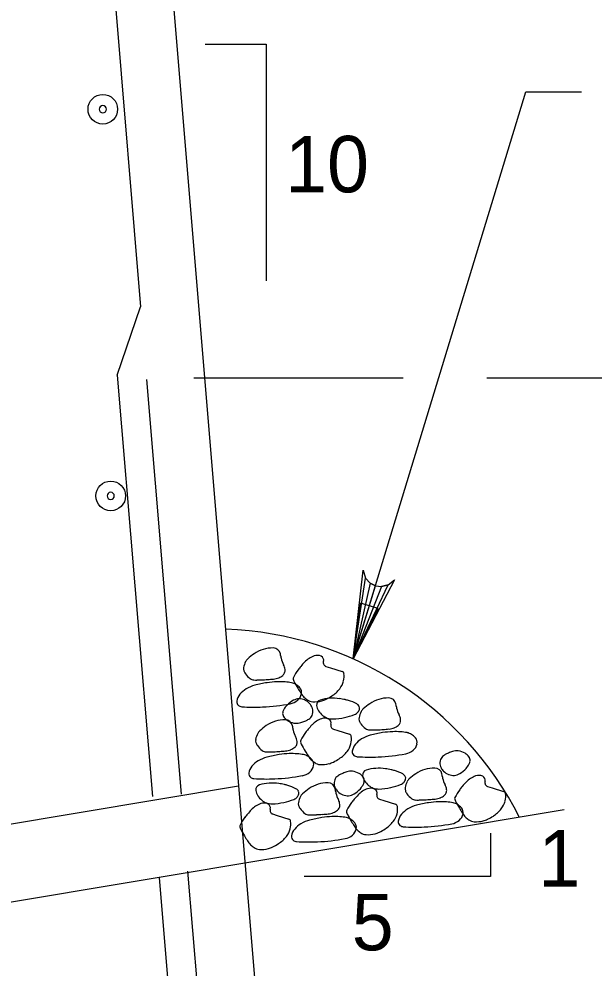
# Model space of a CAD drawing. Extents: x 179 to 454, y -271 to 54.
# Drawn here: x 237.413 to 238.636, y -94.851 to -92.833 of the extents above; entities that cross this region are included whole.
import ezdxf

# ---------------------------------------------------------------- set-up
doc = ezdxf.new("R2010")
doc.units = 0
for name, color, linetype in [('Level 3', 7, 'Continuous'), ('Level 5', 7, 'Continuous'), ('Level 8', 7, 'Continuous'), ('Level 9', 7, 'Continuous')]:
    doc.layers.add(name, color=color, linetype=linetype)

# ---------------------------------------------------------------- blocks, each defined once
blk = doc.blocks.new('B')
at = {"layer": 'Level 3'}
blk.add_circle((0, 0), 0.1066, dxfattribs=at)
for start, end in [(0, 180), (180, 0)]:
    blk.add_arc((0, 0), 0.026, start, end, dxfattribs=at)

msp = doc.modelspace()

# ---------------------------------------------------------------- linework, layer by layer
at = {"layer": 'Level 3'}
for p, q in [((238.1238, -94.194), (238.4913, -92.9877)), ((238.4913, -92.9877), (238.6094, -92.9877)), ((237.7849, -93.5961), (238.2298, -93.5961)), ((238.408, -93.5961), (239.872, -93.5961))]:
    msp.add_line(p, q, dxfattribs=at)
for points in [[(238.1238, -94.194), (238.1447, -94.0055), (238.1501, -94.0222), (238.1598, -94.0328), (238.1712, -94.0386), (238.1838, -94.0402), (238.1979, -94.0367), (238.2116, -94.0258), (238.1238, -94.194), (238.1979, -94.0367), (238.1838, -94.0402), (238.1238, -94.194), (238.1712, -94.0386), (238.1598, -94.0328), (238.1238, -94.194), (238.1501, -94.0222)], [(238.416, -94.5643), (238.416, -94.6567), (238.0191, -94.6567)]]:
    msp.add_lwpolyline(points, dxfattribs=at)
msp.add_lwpolyline([(238.1771, -94.0867), (238.1394, -94.0753), (238.1238, -94.194)], close=True, dxfattribs=at)
at = {"layer": 'Level 5'}
for p, q in [((237.5272, -91.7143), (237.6715, -93.4455)), ((237.6218, -93.5904), (237.6715, -93.4455)), ((237.6218, -93.5904), (237.6965, -94.4864)), ((237.6843, -93.5998), (237.7578, -94.4813)), ((237.7715, -94.6452), (237.9778, -97.1208)), ((237.7109, -94.6589), (237.8529, -96.3632))]:
    msp.add_line(p, q, dxfattribs=at)
at = {"layer": 'Level 8'}
for points in [[(238.0658, -94.2097), (238.0756, -94.2128), (238.1, -94.2205)], [(238.0815, -94.3432), (238.0913, -94.3463), (238.1157, -94.3541)], [(238.4095, -94.4649), (238.4193, -94.468), (238.4437, -94.4757)], [(238.1794, -94.4922), (238.1892, -94.4953), (238.2137, -94.5031)], [(237.9523, -94.5237), (237.9622, -94.5268), (237.9866, -94.5346)]]:
    msp.add_lwpolyline(points, dxfattribs=at)
for centre, radius, start, end in [((237.9791, -94.2804), 0.1177, 124.1443, 132.7374), ((237.9529, -94.2417), 0.0711, 89.5772, 124.1443), ((237.9533, -94.1865), 0.0158, 11.4529, 89.5772), ((237.9159, -94.1941), 0.054, 6.1004, 11.4529), ((238.0057, -94.1845), 0.0363, 186.1004, 192.6291), ((238.058, -94.2365), 0.0519, 109.6635, 136.4562), ((238.0473, -94.2065), 0.0201, 65.9597, 109.6635), ((238.0517, -94.1966), 0.00925, 342.3569, 65.9597), ((237.9408, -94.2226), 0.0514, 153.538, 168.4897), ((237.913, -94.2088), 0.0203, 132.7374, 153.538), ((238.0223, -94.1807), 0.0533, 192.6291, 208.6753), ((237.9511, -94.2197), 0.0278, 6.391, 28.6753), ((238.0974, -94.2824), 0.112, 139.6491, 144.1424), ((238.1811, -94.3535), 0.2218, 136.4562, 139.6491), ((238.0683, -94.2019), 0.0082, 162.3569, 252.4715), ((237.9027, -94.2149), 0.0124, 168.4897, 199.1639), ((237.9119, -94.2117), 0.0222, 199.1639, 207.4728), ((237.9236, -94.2056), 0.0354, 207.4728, 214.0468), ((237.9293, -94.2018), 0.0422, 214.0468, 234.0353), ((237.9547, -94.2071), 0.029, 291.5731, 310.9894), ((237.9639, -94.2177), 0.015, 310.9894, 338.0834), ((237.9651, -94.2181), 0.0138, 338.0834, 6.391), ((238.1187, -94.2978), 0.1383, 144.1424, 152.1777), ((238.0983, -94.2262), 0.00592, 9.0416, 72.4715), ((238.067, -94.2311), 0.0375, 344.9373, 9.0416), ((237.9331, -94.32), 0.0724, 104.9239, 120.8473), ((237.9131, -94.224), 0.0147, 234.0353, 268.2715), ((237.9167, -94.1039), 0.1349, 268.2715, 270.9097), ((237.9812, -94.5007), 0.2594, 99.0416, 104.9239), ((237.9133, -93.889), 0.3498, 270.9097, 272.5478), ((237.9034, -93.6662), 0.5728, 272.5478, 273.846), ((237.9673, -94.4131), 0.1707, 91.7881, 99.0416), ((237.9071, -93.7211), 0.5178, 273.846, 275.2114), ((237.9504, -94.1962), 0.0408, 275.2114, 291.5731), ((237.9672, -94.4105), 0.1681, 86.0442, 91.7881), ((237.9711, -94.355), 0.1125, 79.021, 86.0442), ((237.9872, -94.272), 0.0279, 58.4341, 79.021), ((238.0012, -94.2358), 0.00543, 152.1777, 193.5774), ((238.0147, -94.2325), 0.0193, 193.5774, 207.4728), ((238.2279, -94.1217), 0.2596, 207.4728, 211.2525), ((237.9825, -94.2796), 0.0368, 40.5338, 58.4341), ((238.059, -94.229), 0.0459, 321.7572, 344.9373), ((237.9042, -94.2876), 0.0285, 139.2037, 172.3458), ((237.9239, -94.3047), 0.0546, 120.8473, 139.2037), ((237.99, -94.2634), 0.0242, 309.5539, 349.0625), ((238.5991, -93.8964), 0.6938, 211.2525, 212.2356), ((237.9994, -94.2652), 0.0146, 349.0625, 40.5338), ((238.14, -94.1859), 0.1511, 212.2356, 214.3424), ((238.0399, -94.2139), 0.0702, 303.0692, 321.7572), ((237.8858, -94.2852), 0.00988, 172.3458, 230.2635), ((237.9143, -93.8934), 0.4031, 272.3841, 280.7777), ((238.0205, -94.3279), 0.0518, 117.4803, 136.4654), ((237.9831, -94.255), 0.035, 280.7777, 309.5539), ((238.0093, -94.3064), 0.0276, 91.376, 117.4803), ((238.0093, -94.306), 0.0272, 65.3457, 91.376), ((238.0343, -94.2582), 0.023, 214.3424, 227.6953), ((238.0665, -94.2227), 0.0709, 227.6953, 235.2847), ((238.0076, -94.3097), 0.0312, 41.057, 65.3457), ((238.0391, -94.2623), 0.0228, 235.2847, 266.0442), ((238.0037, -94.3131), 0.0364, 27.4728, 41.057), ((238.0415, -94.2276), 0.0575, 266.0442, 285.2565), ((238.0567, -94.292), 0.011, 106.8084, 186.6218), ((238.0804, -94.3705), 0.0931, 81.3134, 106.8084), ((238.0424, -94.231), 0.054, 285.2565, 295.7443), ((238.0179, -94.1801), 0.1106, 295.7443, 303.0692), ((238.0572, -94.5221), 0.2465, 78.4814, 81.3134), ((238.0882, -94.3701), 0.0913, 73.8272, 78.4814), ((238.0899, -94.3644), 0.0854, 61.1605, 73.8272), ((238.1242, -94.3021), 0.0143, 29.8544, 61.1605), ((238.2249, -94.3866), 0.1177, 124.1443, 132.7374), ((238.1987, -94.348), 0.0711, 89.5772, 124.1443), ((238.1991, -94.2927), 0.0158, 11.4529, 89.5772), ((238.1617, -94.3003), 0.054, 6.1004, 11.4529), ((237.8874, -94.2831), 0.0125, 230.2635, 266.2346), ((237.9138, -93.8823), 0.4142, 266.2346, 272.3841), ((237.9872, -94.3095), 0.0136, 171.9761, 209.5935), ((237.9902, -94.3099), 0.0166, 149.2422, 171.9761), ((238.0206, -94.328), 0.052, 136.4654, 149.2422), ((238.0202, -94.3045), 0.0179, 8.0357, 27.4728), ((238.0151, -94.3052), 0.023, 337.0418, 8.0357), ((238.069, -94.2905), 0.0234, 186.6218, 200.3491), ((238.0737, -94.2888), 0.0285, 200.3491, 212.797), ((238.0867, -94.2804), 0.0439, 212.797, 230.2213), ((238.1192, -94.2939), 0.0197, 292.039, 317.8475), ((238.1227, -94.297), 0.015, 317.8475, 347.2445), ((238.1866, -94.3289), 0.0514, 153.538, 168.4897), ((238.1302, -94.2987), 0.00733, 347.2445, 29.8544), ((238.1588, -94.315), 0.0203, 132.7374, 153.538), ((238.2514, -94.2907), 0.0363, 186.1004, 192.6291), ((238.2681, -94.287), 0.0533, 192.6291, 208.6753), ((237.9787, -94.3946), 0.0711, 89.5772, 124.1443), ((237.9963, -94.3043), 0.024, 209.5935, 237.6667), ((237.9791, -94.3393), 0.0158, 11.4529, 89.5772), ((238.0054, -94.29), 0.041, 237.6667, 259.0544), ((238.0026, -94.3042), 0.0265, 259.0544, 285.7584), ((237.9575, -94.1446), 0.1924, 285.7584, 288.5059), ((238.0026, -94.2791), 0.0505, 288.5059, 293.8705), ((238.0046, -94.2838), 0.0454, 293.8705, 297.4803), ((237.9762, -94.2291), 0.107, 297.4803, 299.831), ((238.0214, -94.3079), 0.0162, 299.831, 337.0418), ((238.0737, -94.37), 0.0519, 109.6635, 136.4562), ((238.0629, -94.3401), 0.0201, 65.9597, 109.6635), ((238.0793, -94.2893), 0.0323, 230.2213, 250.5601), ((238.0792, -94.2895), 0.0321, 250.5601, 271.915), ((238.0674, -94.3301), 0.00925, 342.3569, 65.9597), ((238.0754, -94.1754), 0.1463, 271.915, 281.8686), ((238.0798, -94.1965), 0.1247, 281.8686, 292.039), ((238.1484, -94.3211), 0.0124, 168.4897, 199.1639), ((238.1576, -94.3179), 0.0222, 199.1639, 207.4728), ((238.1693, -94.3118), 0.0354, 207.4728, 214.0468), ((238.2097, -94.3239), 0.015, 310.9894, 338.0834), ((238.1969, -94.3259), 0.0278, 6.391, 28.6753), ((238.2108, -94.3243), 0.0138, 338.0834, 6.391), ((237.9387, -94.3616), 0.0203, 132.7374, 153.538), ((238.0049, -94.4332), 0.1177, 124.1443, 132.7374), ((237.9417, -94.3469), 0.054, 6.1004, 11.4529), ((238.0314, -94.3373), 0.0363, 186.1004, 192.6291), ((238.048, -94.3336), 0.0533, 192.6291, 208.6753), ((238.1344, -94.4314), 0.1383, 144.1424, 152.1777), ((238.1131, -94.416), 0.112, 139.6491, 144.1424), ((238.1968, -94.4871), 0.2218, 136.4562, 139.6491), ((238.084, -94.3354), 0.0082, 162.3569, 252.4715), ((238.175, -94.308), 0.0422, 214.0468, 234.0353), ((238.1588, -94.3303), 0.0147, 234.0353, 268.2715), ((238.1625, -94.2101), 0.1349, 268.2715, 270.9097), ((238.227, -94.6069), 0.2594, 99.0416, 104.9239), ((238.1591, -93.9952), 0.3498, 270.9097, 272.5478), ((238.1491, -93.7725), 0.5728, 272.5478, 273.846), ((238.2131, -94.5193), 0.1707, 91.7881, 99.0416), ((238.1528, -93.8273), 0.5178, 273.846, 275.2114), ((238.1962, -94.3024), 0.0408, 275.2114, 291.5731), ((238.213, -94.5167), 0.1681, 86.0442, 91.7881), ((238.2005, -94.3133), 0.029, 291.5731, 310.9894), ((238.2168, -94.4612), 0.1125, 79.021, 86.0442), ((238.2329, -94.3782), 0.0279, 58.4341, 79.021), ((237.9284, -94.3677), 0.0124, 168.4897, 199.1639), ((237.9665, -94.3755), 0.0514, 153.538, 168.4897), ((237.9376, -94.3645), 0.0222, 199.1639, 207.4728), ((237.9768, -94.3725), 0.0278, 6.391, 28.6753), ((237.9908, -94.371), 0.0138, 338.0834, 6.391), ((238.0169, -94.3693), 0.00543, 152.1777, 193.5774), ((238.0304, -94.3661), 0.0193, 193.5774, 207.4728), ((238.114, -94.3597), 0.00592, 9.0416, 72.4715), ((238.0827, -94.3647), 0.0375, 344.9373, 9.0416), ((238.1697, -94.4109), 0.0546, 120.8473, 139.2037), ((238.1788, -94.4262), 0.0724, 104.9239, 120.8473), ((238.2283, -94.3858), 0.0368, 40.5338, 58.4341), ((238.2451, -94.3714), 0.0146, 349.0625, 40.5338), ((237.9493, -94.3584), 0.0354, 207.4728, 214.0468), ((237.955, -94.3546), 0.0422, 214.0468, 234.0353), ((237.9388, -94.3769), 0.0147, 234.0353, 268.2715), ((237.9424, -94.2568), 0.1349, 268.2715, 270.9097), ((237.939, -94.0418), 0.3498, 270.9097, 272.5478), ((237.9291, -93.8191), 0.5728, 272.5478, 273.846), ((237.9328, -93.8739), 0.5178, 273.846, 275.2114), ((237.9761, -94.349), 0.0408, 275.2114, 291.5731), ((237.9804, -94.3599), 0.029, 291.5731, 310.9894), ((237.9896, -94.3705), 0.015, 310.9894, 338.0834), ((238.2436, -94.2552), 0.2596, 207.4728, 211.2525), ((238.6148, -94.03), 0.6938, 211.2525, 212.2356), ((238.0556, -94.3474), 0.0702, 303.0692, 321.7572), ((238.0747, -94.3625), 0.0459, 321.7572, 344.9373), ((238.15, -94.3939), 0.0285, 139.2037, 172.3458), ((238.1315, -94.3914), 0.00988, 172.3458, 230.2635), ((238.2289, -94.3613), 0.035, 280.7777, 309.5539), ((238.2358, -94.3696), 0.0242, 309.5539, 349.0625), ((238.3973, -94.5729), 0.1924, 108.8812, 111.6288), ((238.3436, -94.4159), 0.0265, 82.1773, 108.8812), ((238.3416, -94.4303), 0.041, 60.7895, 82.1773), ((237.9497, -94.4575), 0.0546, 120.8473, 139.2037), ((237.9588, -94.4728), 0.0724, 104.9239, 120.8473), ((238.007, -94.6535), 0.2594, 99.0416, 104.9239), ((237.993, -94.5659), 0.1707, 91.7881, 99.0416), ((237.9929, -94.5634), 0.1681, 86.0442, 91.7881), ((237.9968, -94.5079), 0.1125, 79.021, 86.0442), ((238.0129, -94.4248), 0.0279, 58.4341, 79.021), ((238.0082, -94.4324), 0.0368, 40.5338, 58.4341), ((238.1557, -94.3194), 0.1511, 212.2356, 214.3424), ((238.0499, -94.3917), 0.023, 214.3424, 227.6953), ((238.0822, -94.3562), 0.0709, 227.6953, 235.2847), ((238.0251, -94.418), 0.0146, 349.0625, 40.5338), ((238.0336, -94.3136), 0.1106, 295.7443, 303.0692), ((238.1332, -94.3894), 0.0125, 230.2635, 266.2346), ((238.1596, -93.9885), 0.4142, 266.2346, 272.3841), ((238.1601, -93.9996), 0.4031, 272.3841, 280.7777), ((238.3311, -94.4156), 0.023, 160.1647, 191.1585), ((238.3247, -94.4133), 0.0162, 122.9538, 160.1647), ((238.3741, -94.4895), 0.107, 120.6031, 122.9538), ((238.3427, -94.4365), 0.0454, 116.9933, 120.6031), ((238.345, -94.441), 0.0505, 111.6288, 116.9933), ((238.3499, -94.4155), 0.024, 32.7163, 60.7895), ((238.3587, -94.4098), 0.0136, 355.0989, 32.7163), ((238.3557, -94.4096), 0.0166, 332.365, 355.0989), ((237.9299, -94.4405), 0.0285, 139.2037, 172.3458), ((238.0157, -94.4162), 0.0242, 309.5539, 349.0625), ((238.0548, -94.3958), 0.0228, 235.2847, 266.0442), ((238.0572, -94.3612), 0.0575, 266.0442, 285.2565), ((238.0581, -94.3646), 0.054, 285.2565, 295.7443), ((238.1546, -94.441), 0.011, 106.8084, 186.6218), ((238.1783, -94.5195), 0.0931, 81.3134, 106.8084), ((238.1552, -94.6711), 0.2465, 78.4814, 81.3134), ((238.1862, -94.5191), 0.0913, 73.8272, 78.4814), ((238.1878, -94.5134), 0.0854, 61.1605, 73.8272), ((238.2966, -94.497), 0.0711, 89.5772, 124.1443), ((238.297, -94.4417), 0.0158, 11.4529, 89.5772), ((238.3261, -94.4166), 0.0179, 191.1585, 210.5956), ((238.342, -94.4071), 0.0364, 210.5956, 224.1798), ((238.3245, -94.3933), 0.0518, 300.6031, 319.5882), ((238.3243, -94.3932), 0.052, 319.5882, 332.365), ((237.9115, -94.438), 0.00988, 172.3458, 230.2635), ((237.9132, -94.436), 0.0125, 230.2635, 266.2346), ((237.9396, -94.0351), 0.4142, 266.2346, 272.3841), ((237.94, -94.0462), 0.4031, 272.3841, 280.7777), ((238.0089, -94.4079), 0.035, 280.7777, 309.5539), ((238.1061, -94.4588), 0.023, 160.1647, 191.1585), ((238.0996, -94.4565), 0.0162, 122.9538, 160.1647), ((238.1491, -94.5327), 0.107, 120.6031, 122.9538), ((238.1177, -94.4797), 0.0454, 116.9933, 120.6031), ((238.12, -94.4842), 0.0505, 111.6288, 116.9933), ((238.1723, -94.6161), 0.1924, 108.8812, 111.6288), ((238.1186, -94.4591), 0.0265, 82.1773, 108.8812), ((238.1166, -94.4735), 0.041, 60.7895, 82.1773), ((238.1249, -94.4587), 0.024, 32.7163, 60.7895), ((238.1669, -94.4395), 0.0234, 186.6218, 200.3491), ((238.1717, -94.4378), 0.0285, 200.3491, 212.797), ((238.1337, -94.453), 0.0136, 355.0989, 32.7163), ((238.2221, -94.4511), 0.0143, 29.8544, 61.1605), ((238.2206, -94.446), 0.015, 317.8475, 347.2445), ((238.2281, -94.4477), 0.00733, 347.2445, 29.8544), ((238.2567, -94.464), 0.0203, 132.7374, 153.538), ((238.3228, -94.5356), 0.1177, 124.1443, 132.7374), ((238.2596, -94.4493), 0.054, 6.1004, 11.4529), ((238.3494, -94.4397), 0.0363, 186.1004, 192.6291), ((238.366, -94.436), 0.0533, 192.6291, 208.6753), ((238.3383, -94.4108), 0.0312, 224.1798, 248.4685), ((238.3368, -94.4145), 0.0272, 248.4685, 274.4988), ((238.3368, -94.4141), 0.0276, 274.4988, 300.6031), ((238.4017, -94.4917), 0.0519, 109.6635, 136.4562), ((238.391, -94.4617), 0.0201, 65.9597, 109.6635), ((238.3954, -94.4518), 0.00925, 342.3569, 65.9597), ((237.9275, -94.4724), 0.011, 106.8084, 186.6218), ((237.9513, -94.551), 0.0931, 81.3134, 106.8084), ((237.9281, -94.7026), 0.2465, 78.4814, 81.3134), ((237.9591, -94.5506), 0.0913, 73.8272, 78.4814), ((237.9607, -94.5449), 0.0854, 61.1605, 73.8272), ((237.995, -94.4826), 0.0143, 29.8544, 61.1605), ((238.0958, -94.5671), 0.1177, 124.1443, 132.7374), ((238.0696, -94.5285), 0.0711, 89.5772, 124.1443), ((238.07, -94.4732), 0.0158, 11.4529, 89.5772), ((238.1011, -94.4598), 0.0179, 191.1585, 210.5956), ((238.0326, -94.4808), 0.054, 6.1004, 11.4529), ((238.117, -94.4504), 0.0364, 210.5956, 224.1798), ((238.0995, -94.4365), 0.0518, 300.6031, 319.5882), ((238.1716, -94.519), 0.0519, 109.6635, 136.4562), ((238.0993, -94.4364), 0.052, 319.5882, 332.365), ((238.1307, -94.4528), 0.0166, 332.365, 355.0989), ((238.1846, -94.4294), 0.0439, 212.797, 230.2213), ((238.1609, -94.4891), 0.0201, 65.9597, 109.6635), ((238.1772, -94.4383), 0.0323, 230.2213, 250.5601), ((238.1771, -94.4385), 0.0321, 250.5601, 271.915), ((238.1653, -94.4791), 0.00925, 342.3569, 65.9597), ((238.1733, -94.3244), 0.1463, 271.915, 281.8686), ((238.1778, -94.3455), 0.1247, 281.8686, 292.039), ((238.2172, -94.4429), 0.0197, 292.039, 317.8475), ((238.2464, -94.4701), 0.0124, 168.4897, 199.1639), ((238.2845, -94.4779), 0.0514, 153.538, 168.4897), ((238.2948, -94.4749), 0.0278, 6.391, 28.6753), ((238.3088, -94.4733), 0.0138, 338.0834, 6.391), ((238.4624, -94.553), 0.1383, 144.1424, 152.1777), ((238.4411, -94.5376), 0.112, 139.6491, 144.1424), ((238.5248, -94.6087), 0.2218, 136.4562, 139.6491), ((238.412, -94.4571), 0.0082, 162.3569, 252.4715), ((237.9399, -94.471), 0.0234, 186.6218, 200.3491), ((237.9446, -94.4693), 0.0285, 200.3491, 212.797), ((237.9575, -94.4609), 0.0439, 212.797, 230.2213), ((237.9507, -94.377), 0.1247, 281.8686, 292.039), ((237.9901, -94.4744), 0.0197, 292.039, 317.8475), ((237.9935, -94.4775), 0.015, 317.8475, 347.2445), ((238.0574, -94.5094), 0.0514, 153.538, 168.4897), ((238.001, -94.4792), 0.00733, 347.2445, 29.8544), ((238.0296, -94.4955), 0.0203, 132.7374, 153.538), ((238.1223, -94.4712), 0.0363, 186.1004, 192.6291), ((238.1389, -94.4675), 0.0533, 192.6291, 208.6753), ((238.1133, -94.454), 0.0312, 224.1798, 248.4685), ((238.1118, -94.4577), 0.0272, 248.4685, 274.4988), ((238.1118, -94.4573), 0.0276, 274.4988, 300.6031), ((238.2111, -94.565), 0.112, 139.6491, 144.1424), ((238.2948, -94.6361), 0.2218, 136.4562, 139.6491), ((238.182, -94.4844), 0.0082, 162.3569, 252.4715), ((238.2556, -94.4669), 0.0222, 199.1639, 207.4728), ((238.2673, -94.4608), 0.0354, 207.4728, 214.0468), ((238.273, -94.457), 0.0422, 214.0468, 234.0353), ((238.2568, -94.4793), 0.0147, 234.0353, 268.2715), ((238.2508, -93.9763), 0.5178, 273.846, 275.2114), ((238.2941, -94.4514), 0.0408, 275.2114, 291.5731), ((238.2984, -94.4623), 0.029, 291.5731, 310.9894), ((238.3076, -94.4729), 0.015, 310.9894, 338.0834), ((238.3449, -94.491), 0.00543, 152.1777, 193.5774), ((238.3584, -94.4878), 0.0193, 193.5774, 207.4728), ((238.442, -94.4814), 0.00592, 9.0416, 72.4715), ((238.4108, -94.4863), 0.0375, 344.9373, 9.0416), ((237.9445, -94.5505), 0.0519, 109.6635, 136.4562), ((237.9338, -94.5205), 0.0201, 65.9597, 109.6635), ((237.9501, -94.4698), 0.0323, 230.2213, 250.5601), ((237.9501, -94.47), 0.0321, 250.5601, 271.915), ((237.9382, -94.5106), 0.00925, 342.3569, 65.9597), ((237.9462, -94.3559), 0.1463, 271.915, 281.8686), ((238.0193, -94.5016), 0.0124, 168.4897, 199.1639), ((238.0285, -94.4984), 0.0222, 199.1639, 207.4728), ((238.0402, -94.4923), 0.0354, 207.4728, 214.0468), ((238.0459, -94.4885), 0.0422, 214.0468, 234.0353), ((238.0805, -94.5044), 0.015, 310.9894, 338.0834), ((238.0677, -94.5064), 0.0278, 6.391, 28.6753), ((238.0817, -94.5048), 0.0138, 338.0834, 6.391), ((238.2324, -94.5803), 0.1383, 144.1424, 152.1777), ((238.2119, -94.5087), 0.00592, 9.0416, 72.4715), ((238.1807, -94.5137), 0.0375, 344.9373, 9.0416), ((238.2677, -94.5599), 0.0546, 120.8473, 139.2037), ((238.2768, -94.5752), 0.0724, 104.9239, 120.8473), ((238.2604, -94.3591), 0.1349, 268.2715, 270.9097), ((238.325, -94.7559), 0.2594, 99.0416, 104.9239), ((238.257, -94.1442), 0.3498, 270.9097, 272.5478), ((238.2471, -93.9214), 0.5728, 272.5478, 273.846), ((238.311, -94.6683), 0.1707, 91.7881, 99.0416), ((238.3109, -94.6657), 0.1681, 86.0442, 91.7881), ((238.3148, -94.6102), 0.1125, 79.021, 86.0442), ((238.3309, -94.5272), 0.0279, 58.4341, 79.021), ((238.5716, -94.3769), 0.2596, 207.4728, 211.2525), ((238.3262, -94.5348), 0.0368, 40.5338, 58.4341), ((238.9428, -94.1516), 0.6938, 211.2525, 212.2356), ((238.3431, -94.5204), 0.0146, 349.0625, 40.5338), ((238.3836, -94.4691), 0.0702, 303.0692, 321.7572), ((238.4027, -94.4842), 0.0459, 321.7572, 344.9373), ((238.0053, -94.6118), 0.1383, 144.1424, 152.1777), ((237.984, -94.5965), 0.112, 139.6491, 144.1424), ((238.0677, -94.6676), 0.2218, 136.4562, 139.6491), ((237.9549, -94.5159), 0.0082, 162.3569, 252.4715), ((238.0297, -94.5108), 0.0147, 234.0353, 268.2715), ((238.0333, -94.3906), 0.1349, 268.2715, 270.9097), ((238.0979, -94.7874), 0.2594, 99.0416, 104.9239), ((238.0299, -94.1757), 0.3498, 270.9097, 272.5478), ((238.02, -93.9529), 0.5728, 272.5478, 273.846), ((238.0839, -94.6998), 0.1707, 91.7881, 99.0416), ((238.0237, -94.0078), 0.5178, 273.846, 275.2114), ((238.067, -94.4829), 0.0408, 275.2114, 291.5731), ((238.0838, -94.6972), 0.1681, 86.0442, 91.7881), ((238.0713, -94.4938), 0.029, 291.5731, 310.9894), ((238.0877, -94.6417), 0.1125, 79.021, 86.0442), ((238.1038, -94.5587), 0.0279, 58.4341, 79.021), ((238.1149, -94.5183), 0.00543, 152.1777, 193.5774), ((238.1283, -94.5151), 0.0193, 193.5774, 207.4728), ((238.3416, -94.4042), 0.2596, 207.4728, 211.2525), ((238.1727, -94.5115), 0.0459, 321.7572, 344.9373), ((238.2479, -94.5428), 0.0285, 139.2037, 172.3458), ((238.3337, -94.5186), 0.0242, 309.5539, 349.0625), ((238.4838, -94.4411), 0.1511, 212.2356, 214.3424), ((238.378, -94.5134), 0.023, 214.3424, 227.6953), ((238.4102, -94.4779), 0.0709, 227.6953, 235.2847), ((238.3616, -94.4353), 0.1106, 295.7443, 303.0692), ((237.8878, -94.5498), 0.00543, 152.1777, 193.5774), ((237.9012, -94.5466), 0.0193, 193.5774, 207.4728), ((237.9848, -94.5402), 0.00592, 9.0416, 72.4715), ((237.9536, -94.5452), 0.0375, 344.9373, 9.0416), ((238.0406, -94.5914), 0.0546, 120.8473, 139.2037), ((238.0497, -94.6067), 0.0724, 104.9239, 120.8473), ((238.0991, -94.5663), 0.0368, 40.5338, 58.4341), ((238.7127, -94.179), 0.6938, 211.2525, 212.2356), ((238.2537, -94.4684), 0.1511, 212.2356, 214.3424), ((238.116, -94.5519), 0.0146, 349.0625, 40.5338), ((238.1535, -94.4964), 0.0702, 303.0692, 321.7572), ((238.2295, -94.5404), 0.00988, 172.3458, 230.2635), ((238.2312, -94.5384), 0.0125, 230.2635, 266.2346), ((238.2575, -94.1375), 0.4142, 266.2346, 272.3841), ((238.258, -94.1486), 0.4031, 272.3841, 280.7777), ((238.3268, -94.5103), 0.035, 280.7777, 309.5539), ((238.3828, -94.5175), 0.0228, 235.2847, 266.0442), ((238.3852, -94.4828), 0.0575, 266.0442, 285.2565), ((238.3861, -94.4862), 0.054, 285.2565, 295.7443), ((238.1145, -94.4357), 0.2596, 207.4728, 211.2525), ((238.4856, -94.2105), 0.6938, 211.2525, 212.2356), ((237.9264, -94.5279), 0.0702, 303.0692, 321.7572), ((237.9456, -94.543), 0.0459, 321.7572, 344.9373), ((238.0024, -94.5719), 0.00988, 172.3458, 230.2635), ((238.0208, -94.5743), 0.0285, 139.2037, 172.3458), ((238.0998, -94.5417), 0.035, 280.7777, 309.5539), ((238.1066, -94.5501), 0.0242, 309.5539, 349.0625), ((238.1479, -94.5407), 0.023, 214.3424, 227.6953), ((238.1802, -94.5052), 0.0709, 227.6953, 235.2847), ((238.1527, -94.5448), 0.0228, 235.2847, 266.0442), ((238.1551, -94.5102), 0.0575, 266.0442, 285.2565), ((238.1561, -94.5136), 0.054, 285.2565, 295.7443), ((238.1315, -94.4626), 0.1106, 295.7443, 303.0692), ((238.0266, -94.4999), 0.1511, 212.2356, 214.3424), ((237.9208, -94.5722), 0.023, 214.3424, 227.6953), ((237.9531, -94.5367), 0.0709, 227.6953, 235.2847), ((237.929, -94.545), 0.054, 285.2565, 295.7443), ((237.9044, -94.4941), 0.1106, 295.7443, 303.0692), ((238.0041, -94.5698), 0.0125, 230.2635, 266.2346), ((238.0305, -94.169), 0.4142, 266.2346, 272.3841), ((238.0309, -94.1801), 0.4031, 272.3841, 280.7777), ((237.9257, -94.5763), 0.0228, 235.2847, 266.0442), ((237.9281, -94.5417), 0.0575, 266.0442, 285.2565)]:
    msp.add_arc(centre, radius, start, end, dxfattribs=at)
at = {"layer": 'Level 9'}
for p, q in [((237.5865, -90.944), (238.0433, -96.4247)), ((237.8799, -94.4645), (236.8483, -94.6364)), ((238.5729, -94.5152), (236.8483, -94.8027))]:
    msp.add_line(p, q, dxfattribs=at)
msp.add_lwpolyline([(237.809, -92.8867), (237.9382, -92.8867), (237.9382, -93.3901)], dxfattribs=at)
msp.add_arc((237.8241, -94.8632), 0.7333, 26.9324, 87.7453, dxfattribs=at)

# ---------------------------------------------------------------- block references
at = {"layer": 'Level 3', "xscale": 0.29527500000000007, "yscale": 0.29527500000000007, "rotation": 90}
for p in [(237.591, -93.025), (237.6078, -93.8473)]:
    msp.add_blockref('B', p, dxfattribs=at)

# ---------------------------------------------------------------- texts
at = {"layer": 'Level 3'}
for s, p in [('10', (237.9788, -93.2017)), ('1', (238.5175, -94.678)), ('5', (238.1206, -94.8136))]:
    msp.add_text(s, height=0.12, dxfattribs=at).set_placement(p)

doc.saveas('drawing.dxf')
